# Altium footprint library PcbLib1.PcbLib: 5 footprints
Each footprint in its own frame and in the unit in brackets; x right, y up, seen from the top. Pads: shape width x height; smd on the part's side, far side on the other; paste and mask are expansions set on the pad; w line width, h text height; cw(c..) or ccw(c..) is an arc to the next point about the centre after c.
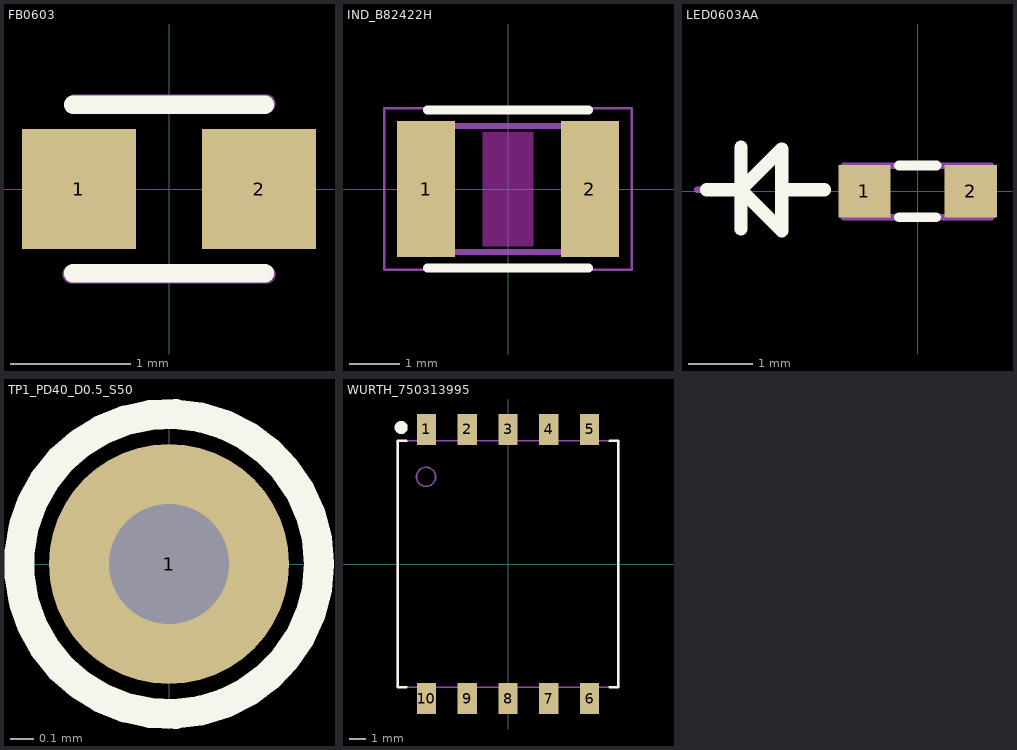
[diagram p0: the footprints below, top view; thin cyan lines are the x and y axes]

## FB0603 [mm]
height 0.95
pads (2):
  rect 0.95x1 smd: 1(-0.75,0) 2(0.75,0)
Top Overlay:
  lines w0.152: -0.8,-0.703 0.8,-0.703 ; -0.8,0.703 0.8,0.703
Mechanical 5:
  lines w0.152: -0.813,-0.711 0.813,-0.711 ; -0.787,0.711 0.813,0.711
  text ".Designator" at -0.864,-0.381 h0.76
Mechanical 15:
  lines w0.025: -0.8,-0.4 -0.8,0.4 ; 0.8,-0.4 0.8,0.4
  lines w0.1: -0.8,-0.4 -0.8,0.4

## IND_B82422H [mm]
height 2.4
pads (2):
  rect 1.15x2.7 smd: 1(-1.625,0) 2(1.625,0)
Top Layer keep-out:
  rectangle: -0.508,-1.136 0.508,1.13
Top Overlay:
  lines w0.178: -1.6,-1.566 1.6,-1.566 ; -1.6,1.566 1.6,1.566
Mechanical 5:
  lines w0.127: -1.6,-1.25 -1.6,1.25 1.6,1.25 1.6,-1.25 -1.6,-1.25
  text ".Designator" at -0.584,-0.33 h0.76
Mechanical 15:
  lines w0.05: -2.45,-1.6 -2.45,1.6 2.45,1.6 2.45,-1.6 -2.45,-1.6
3D body: height 2.4, standoff 0, extent -1.6,-1.25 1.6,1.25

## LED0603AA [mil]
pads (2):
  rect 32x32 smd: 1(-32.48,0) 2(32.48,0)
Top Overlay:
  lines w6: -11.42,-15.75 11.42,-15.75 ; -11.42,15.75 11.42,15.75
  lines w8: -129,1 -108,1 ; -108,-23 -108,27 ; -82,1 -57,1 ; -108,1 -83,26 -83,-24 -108,1
Mechanical 5:
  lines w4: -45,-15.75 -45,15.75 45,15.75 45,-15.75 -45,-15.75
  text ".Designator" at -36,26 h40
Mechanical 15:
  lines w1: -31.5,-15.75 31.5,-15.75 31.5,15.75 -31.5,15.75 -31.5,-15.75
  lines w3.94: -134.79,0.96 -109.79,0.96 ; -109.79,-24.04 -109.79,25.96 ; -84.79,0.96 -59.79,0.96 ; -109.79,0.96 -84.79,25.96 -84.79,-24.04 -109.79,0.96

## TP1_PD40_D0.5_S50 [mil]
height 1.4
pads (1):
  round 40 hole 20: 1(0,0)
Top Overlay:
  circle w5: c0,0 r25

## WURTH_750313995 [mm] "WURTH"
height 12.7
pads (10):
  rect 1.17x1.88 smd: 1(-4.96,8.18) 2(-2.48,8.18) 3(0,8.18) 4(2.48,8.18) 5(4.96,8.18) 6(4.96,-8.18) 7(2.48,-8.18) 8(0,-8.18) 9(-2.48,-8.18) 10(-4.96,-8.18)
Top Overlay:
  circle w0.4: c-6.5,8.3 r0.2
  lines w0.152: -6.2,-7.5 -6.7,-7.5 -6.7,7.5 -6.4,7.5 -6.2,7.5 ; 6.2,-7.5 6.7,-7.5 6.7,-5.8 6.7,7.5 6.4,7.5 6.2,7.5
Mechanical 5:
  circle w0.1: c-4.983,5.3 r0.583
  lines w0.1: -5.3,-7.5 -5.3,-8.9 -4.6,-8.9 -4.6,-7.5 ; -5.3,7.5 -5.3,8.9 -4.6,8.9 -4.6,7.5 ; -2.8,-7.5 -2.8,-8.9 -2.1,-8.9 -2.1,-7.5 ; -2.8,7.5 -2.8,8.9 -2.1,8.9 -2.1,7.5 ; -0.3,-7.5 -0.3,-8.9 0.4,-8.9 0.4,-7.5 ; -0.3,7.5 -0.3,8.9 0.4,8.9 0.4,7.5 ; 2.1,-7.5 2.1,-8.9 2.8,-8.9 2.8,-7.5 ; 2.1,7.5 2.1,8.9 2.8,8.9 2.8,7.5 ; 4.6,-7.5 4.6,-8.9 5.3,-8.9 5.3,-7.5 ; 4.6,7.5 4.6,8.9 5.3,8.9 5.3,7.5 ; -6.73,-7.5 6.73,-7.5 6.73,7.5 -6.73,7.5 -6.73,-7.5
  text ".Designator" at -1.016,-0.127 h1.27
3D body: height 12.7, standoff 0, extent -6.729,-7.499 6.729,7.499
3D body: height 1.2, standoff 0, extent -5.299,-8.899 -4.601,-7.501
3D body: height 1.2, standoff 0, extent -2.799,-8.899 -2.101,-7.501
3D body: height 1.2, standoff 0, extent -5.299,7.501 -4.601,8.899
3D body: height 1.2, standoff 0, extent -2.799,7.501 -2.101,8.899
3D body: height 1.2, standoff 0, extent -0.299,-8.899 0.399,-7.501
3D body: height 1.2, standoff 0, extent 2.101,-8.899 2.799,-7.501
3D body: height 1.2, standoff 0, extent 4.601,-8.899 5.299,-7.501
3D body: height 1.2, standoff 0, extent -0.299,7.501 0.399,8.899
3D body: height 1.2, standoff 0, extent 2.101,7.501 2.799,8.899
3D body: height 1.2, standoff 0, extent 4.601,7.501 5.299,8.899
3D body: height 12.7, standoff 10, extent -5.577,4.706 -4.389,5.894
